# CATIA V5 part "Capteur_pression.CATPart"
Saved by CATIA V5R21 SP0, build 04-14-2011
Part number: Capteur_pression
Bounding box of the stored display mesh (mm): x -16.5 to 6.29, y -7.35 to 7.35, z -6.15 to 6.15
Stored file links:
  C:\Users\zerma\Pictures\CAO\Capteur_pression.CATPart
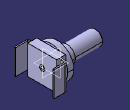
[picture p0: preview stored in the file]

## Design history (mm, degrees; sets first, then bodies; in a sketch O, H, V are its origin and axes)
Body1 (main body)
  Sketch1 on yz-plane, origin (0, 0, 0), H (0, 1, 0), V (0, 0, 1)
    line L1 (5.35, 5.35) -> (5.35, -5.35)
    line L2 (5.35, -5.35) -> (-5.35, -5.35)
    line L3 (-5.35, -5.35) -> (-5.35, 5.35)
    line L4 (-5.35, 5.35) -> (5.35, 5.35)
    length L1 = 10.7
    length L4 = 10.7
    vertical: L1 V, L3 V
    horizontal: L2 H, L4 H
    equidistance: L1 L3 O, L2 L4 O
  Pad1: profile Sketch1, direction (1, 0, 0), length 3.34
  Sketch2 on start face of Pad1, origin (0, 0, 0), H (0, -1, 0), V (0, 0, 1)
    circle A1 centre (0, 0) radius 6.15
    radius A1 = 6.15
  Pad2: profile Sketch2, direction (-1, 0, 0), length 2.2
  Sketch3 on end face of Pad2, origin (-2.2, 0, 0), H (0, -1, 0), V (0, 0, 1)
    circle A1 centre (0, 0) radius 3.11
    radius A1 = 3.11
  Pad3: profile Sketch3, direction (-1, 0, 0), length 3.6
  Fillet1: radius 0.5, on edge [end face of Pad2 | face of Pad3 from Sketch3.A1]
  Sketch4 on end face of Pad3, origin (-5.8, 0, 0), H (0, -1, 0), V (0, 0, 1)
    circle A1 centre (0, 0) radius 2.7
    radius A1 = 2.7
  Pad4: profile Sketch4, direction (-1, 0, 0), length 10.7
  Fillet2: radius 0.25, on edge [end face of Pad3 | face of Pad4 from Sketch4.A1]; edge [face of Pad4 from Sketch4.A1 | end face of Pad4]
  Sketch5 on end face of Pad4, origin (-16.5, 0, 0), H (0, -1, 0), V (0, 0, 1)
    circle A1 centre (0, 0) radius 0.8
    radius A1 = 0.8
  Pocket1: profile Sketch5, direction (1, 0, 0), length 5
  Sketch6 on end face of Pad1, origin (3.34, 0, 0), H (0, 1, 0), V (0, 0, 1)
    spline S1 through (0, -1) (0.27, -0.27) (1, 0)
    spline S2 through (0, -1) (-0.27, -0.27) (-1, 0)
    spline S3 through (0, 1) (0.27, 0.27) (1, 0)
    spline S4 through (0, 1) (-0.27, 0.27) (-1, 0)
    point P1 (0, -1)
    point P2 (0.27, -0.27)
    point P3 (1, 0)
    point P4 (-1, 0)
    point P5 (0, -1)
    point P6 (-0.27, -0.27)
    point P7 (1, 0)
    point P8 (0, 1)
    point P9 (0.27, 0.27)
    point P10 (-1, 0)
    point P11 (0, 1)
    point P12 (-0.27, 0.27)
    symmetry: S1 S2 V, P3 P4 V, P1 P5 V, P2 P6 V, S1 S3 H, P3 P7 H, P1 P8 H, P2 P9 H, S3 S4 V, P7 P10 V, P8 P11 V, P9 P12 V
    coincidence: P1 P5, P3 P7, P4 P10, P8 P11
  Pocket2: profile Sketch6, direction (-1, 0, 0), length 3
  Sketch7 on end face of Pad1, origin (3.34, 0, 0), H (0, 1, 0), V (0, 0, 1)
    circle A1 centre (0, 0) radius 1
    radius A1 = 1
  Pocket3: profile Sketch7, direction (-1, 0, 0), length 0.1
  Sketch8 on face of Pad1 from Sketch1.L1, origin (0, 5.35, 0), H (-1, 0, 0), V (0, 0, 1)
    line L1 (-1.84, 4.65) -> (-1.29, 4.65)
    line L2 (-1.29, 4.65) -> (-1.29, -4.65)
    line L3 (-1.29, -4.65) -> (-1.84, -4.65)
    line L4 (-1.84, -4.65) -> (-1.84, 4.65)
    reference projected line E1 (0, 5.35) -> (-3.34, 5.35) from edge [face of Pad1 from Sketch1.L4 | face of Pad1 from Sketch1.L1]
    reference projected line E2 (0, -5.35) -> (-3.34, -5.35) from edge [face of Pad1 from Sketch1.L1 | face of Pad1 from Sketch1.L2]
    reference projected line E3 (-3.34, -5.35) -> (-3.34, 5.35) from edge [face of Pad1 from Sketch1.L1 | end face of Pad1]
    distance L1 E1 = 0.7
    distance L3 E2 = 0.7
    distance L4 E3 = 1.5
    distance L4 L2 = 0.55
    horizontal: L1 H, L3 H
    vertical: L2 V, L4 V
  Pad5: profile Sketch8, direction (0, 1, 0), length 2
  Sketch9 on face of Pad5 from Sketch8.L2, origin (1.29, 0, 0), H (0, -1, 0), V (0, 0, 1)
    line L1 (-6.85, 4.65) -> (-7.35, 4.65)
    line L2 (-7.35, 4.65) -> (-7.35, -4.65)
    line L3 (-7.35, -4.65) -> (-6.85, -4.65)
    line L4 (-6.85, -4.65) -> (-6.85, 4.65)
    reference projected line E1 (-7.35, -4.65) -> (-7.35, 4.65) from edge [face of Pad5 from Sketch8.L2 | end face of Pad5]
    reference projected line E2 (-5.35, 4.65) -> (-7.35, 4.65) from edge [face of Pad5 from Sketch8.L1 | face of Pad5 from Sketch8.L2]
    reference projected line E3 (-5.35, -4.65) -> (-7.35, -4.65) from edge [face of Pad5 from Sketch8.L2 | face of Pad5 from Sketch8.L3]
    distance L4 L2 = 0.5
    horizontal: L1 H, L3 H
    vertical: L2 V, L4 V
    coincidence: L2 E1, E2 L1, L3 E3
  Pad6: profile Sketch9, direction (1, 0, 0), length 5
  Fillet3: radius 1, on edge [face of Pad6 | face of Pad6]
  Mirror1: of Pad5, Pad6, Fillet3, about zx-plane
